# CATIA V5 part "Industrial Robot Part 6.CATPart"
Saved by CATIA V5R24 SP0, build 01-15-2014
Part number: Industrial Robot Part 6
Material "Dark Green": density 7860 kg/m3, Young's modulus 2e+11 Pa, Poisson ratio 0.266
Bounding box of the stored display mesh (mm): x -475.729 to 456.635, y -587.21 to 829.1, z -531.758 to 383.442
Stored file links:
  C:\Users\cdl\Downloads\2024_CAD_final\p2\Industrial Robot Part 6.CATPart
  D:\Program Files\Dassault Systemes\B24\win_b64\startup\materials\Catalog.CATMaterial
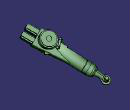
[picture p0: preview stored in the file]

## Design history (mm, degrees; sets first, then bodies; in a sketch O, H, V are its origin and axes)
Body1 (main body), material "Dark Green"
  Body2 "Solid 1"
    Solid1: solid without history
  Assemble1: tool Body2
  Body3 "Solid 2"
    Solid2 "Solid.1": solid without history
  Assemble2: tool Body3
  Body4 "Solid 3"
    Solid3 "Solid.1": solid without history
  Assemble3: tool Body4
  Body5 "Solid 4"
    Solid4 "Solid.1": solid without history
  Assemble4: tool Body5
  Body6 "Solid 5"
    Solid5 "Solid.1": solid without history
  Assemble5: tool Body6
  Translate1: Direction (0, 0, 1), Length -1825, ToTransfor Assemble5
  Translate2: Direction (1, 0, 0), Length -587, ToTransfor Translate1
  Rotate1: Axis Z axis, Angle 147.5672, ToTransfor Translate2
  Rotate2: Axis Y axis, Angle 300.5672, ToTransfor Rotate1
  Rotate3: Axis X axis, Angle 24.5672, ToTransfor Rotate2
